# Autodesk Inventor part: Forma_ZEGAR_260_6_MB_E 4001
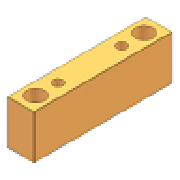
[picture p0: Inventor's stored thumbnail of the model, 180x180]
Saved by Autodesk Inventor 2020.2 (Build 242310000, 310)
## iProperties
IsCustomPart: 1
Manager: www.cadconsulting.pl
Company: Fabian Stasiak CAD Consulting
Created: 2014-02
Part Number: Forma_ZEGAR_260_6_MB_E 4001
Material: S 55 C
Description: Spacer Block
Document SubType Name: Modeling
Designer: F.Stasiak
Standard Revision: 1
Manufacturer: DME
Language: pl-PL
Size Designation: 496x346x76
Categories: <MemberInstance><Categories><Category DisplayName="Forma wtryskowa" InternalName="349578f2-f4d4-4954-8c09-8e99297a61c0" Mnemonic="MOLD"><Category DisplayName="P
Density: 7.85 g/cm^3
Appearance: Orange (Pale)
Catalog Web Link: www.expertbooks.pl
Author: F.Stasiak
Subject: Zbiór ćwiczeń. Autodesk Inventor 2020. Kurs Professional
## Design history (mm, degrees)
sketch "Sketch1"
  geometry: L1 (-111, 248)-(-173, 248); L2 (-173, 248)-(-173, -248); L3 (-173, -248)-(-111, -248); L4 (-111, -248)-(-111, 248); L5 (173, 248)-(173, -248); L6 (111, -248)-(111, 248); L7 (111, 248)-(173, 248); L8 (111, -248)-(173, -248); 7 further points
  constraints: 16 end point, 3 parallel, 2 horizontal alignment, 2 midpoint, 2 perpendicular, 1 horizontal, 1 vertical
  dimensions: "d85" = 496 distance between parallel lines of L3 L1 (= L); "d86" = 62 distance between parallel lines of L4 L2 (= W_); "d88" = 62 distance between parallel lines of L5 L6 (= W_); "d89" = 173 distance from line of point (0, 0) L2 (= 0.5 x M_W); "d93" = 496 distance between parallel lines of L8 L7 (= L); "d94" = 173 distance from line of point (0, 0) L5 (= 0.5 x M_W); "d98" = 165 vertical distance of point (-137, 165) point (0, 0) (= 0.5 x S1_L); "d100" = 137 horizontal distance of point (-137, 165) point (0, 0) (= 0.5 x S1_W); "d101" = 137 horizontal distance of point (137, 165) point (0, 0) (= 0.5 x S1_W); "d102" = 165 vertical distance of point (0, 0) point (137, 165) (= 0.5 x S1_L); "d103" = 137 horizontal distance of point (-137, 208) point (0, 0) (= 0.5 x LS_W); "d105" = 208 vertical distance of point (-137, 208) point (0, 0) (= 0.5 x LS_L); "d106" = 137 horizontal distance of point (0, 0) point (137, 208) (= 0.5 x LS_W); "d107" = 208 vertical distance of point (137, 208) point (0, 0) (= 0.5 x LS_L)
extrude "Extrusion1" new body sketch "Sketch1" distance "d20" = 76 (= H_); taper "d30" = 0 deg
extrude "Extrusion2" join sketch "Sketch1" distance "d95" = 76 (= H_); taper "d96" = 0 deg
hole "Hole1" sketch "Sketch1" diameter "d129" = 18 (= S1_d1); stored, may be unused: countersink angle "d133" = 90 deg, drill point angle "d135" = 0 deg; dims "d130" = 6, "d131" = 4, "d132" = 2, "d134" = 76 (= H_)
pattern_linear "Rectangular Pattern1" dims "d156" = 330 (computed from S1_L, Ns)
hole "Hole2" sketch "Sketch1" diameter "d108" = 42 (= LS_d); stored, may be unused: countersink angle "d112" = 90 deg, drill point angle "d114" = 0 deg; dims "d109" = 6, "d110" = 4, "d111" = 2, "d113" = 76 (= H_)
pattern_linear "Rectangular Pattern2" dims "d138" = 416 (computed from LS_L, Nl)
hole "Hole3" sketch "Sketch1" diameter "d122" = 18 (= S1_d1); stored, may be unused: countersink angle "d126" = 90 deg, drill point angle "d128" = 0 deg; dims "d123" = 6, "d124" = 4, "d125" = 2, "d127" = 76 (= H_)
pattern_linear "Rectangular Pattern3" dims "d153" = 330 (computed from S1_L, Ns)
hole "Hole4" sketch "Sketch1" diameter "d115" = 42 (= LS_d); stored, may be unused: countersink angle "d119" = 90 deg, drill point angle "d121" = 0 deg; dims "d116" = 6, "d117" = 4, "d118" = 2, "d120" = 76 (= H_)
pattern_linear "Rectangular Pattern4" dims "d150" = 416 (computed from LS_L, Nl)
workplane "Work Plane1"
workplane "Work Plane2"
chamfer "Chamfer1" distance "d82" = 0.5; stored, may be unused: second distance "d83" = 2, angle "d84" = 45 deg
chamfer "Chamfer2" distance "d157" = 0.5; stored, may be unused: second distance "d158" = 2, angle "d159" = 45 deg
body "Solid1"
other parameters: "L" = 496 [user parameter; used in 2 equation terms], "W_" = 62 [user parameter; used in 2 equation terms], "H_" = 76 [user parameter; used in 7 equation terms], "M_W" = 346 [user parameter; used in 2 equation terms], "S1_W" = 274 [user parameter; used in 2 equation terms], "S1_d1" = 18 [user parameter; used in 2 equation terms], "LS_L" = 416 [user parameter; used in 4 equation terms], "LS_W" = 274 [user parameter; used in 2 equation terms], "LS_d" = 42 [user parameter; used in 2 equation terms], "d160" = 0, "d161" = 76 (= H_)
